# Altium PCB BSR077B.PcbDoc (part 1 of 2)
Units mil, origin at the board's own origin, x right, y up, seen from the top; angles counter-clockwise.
Board outline 2900 x 1600 mil, 4 copper layers (Top Layer, Signal Layer 1, Signal Layer 2, Bottom Layer), stack 40 mil thick; 58 components, 11 nets, 111 pads, 62 vias.
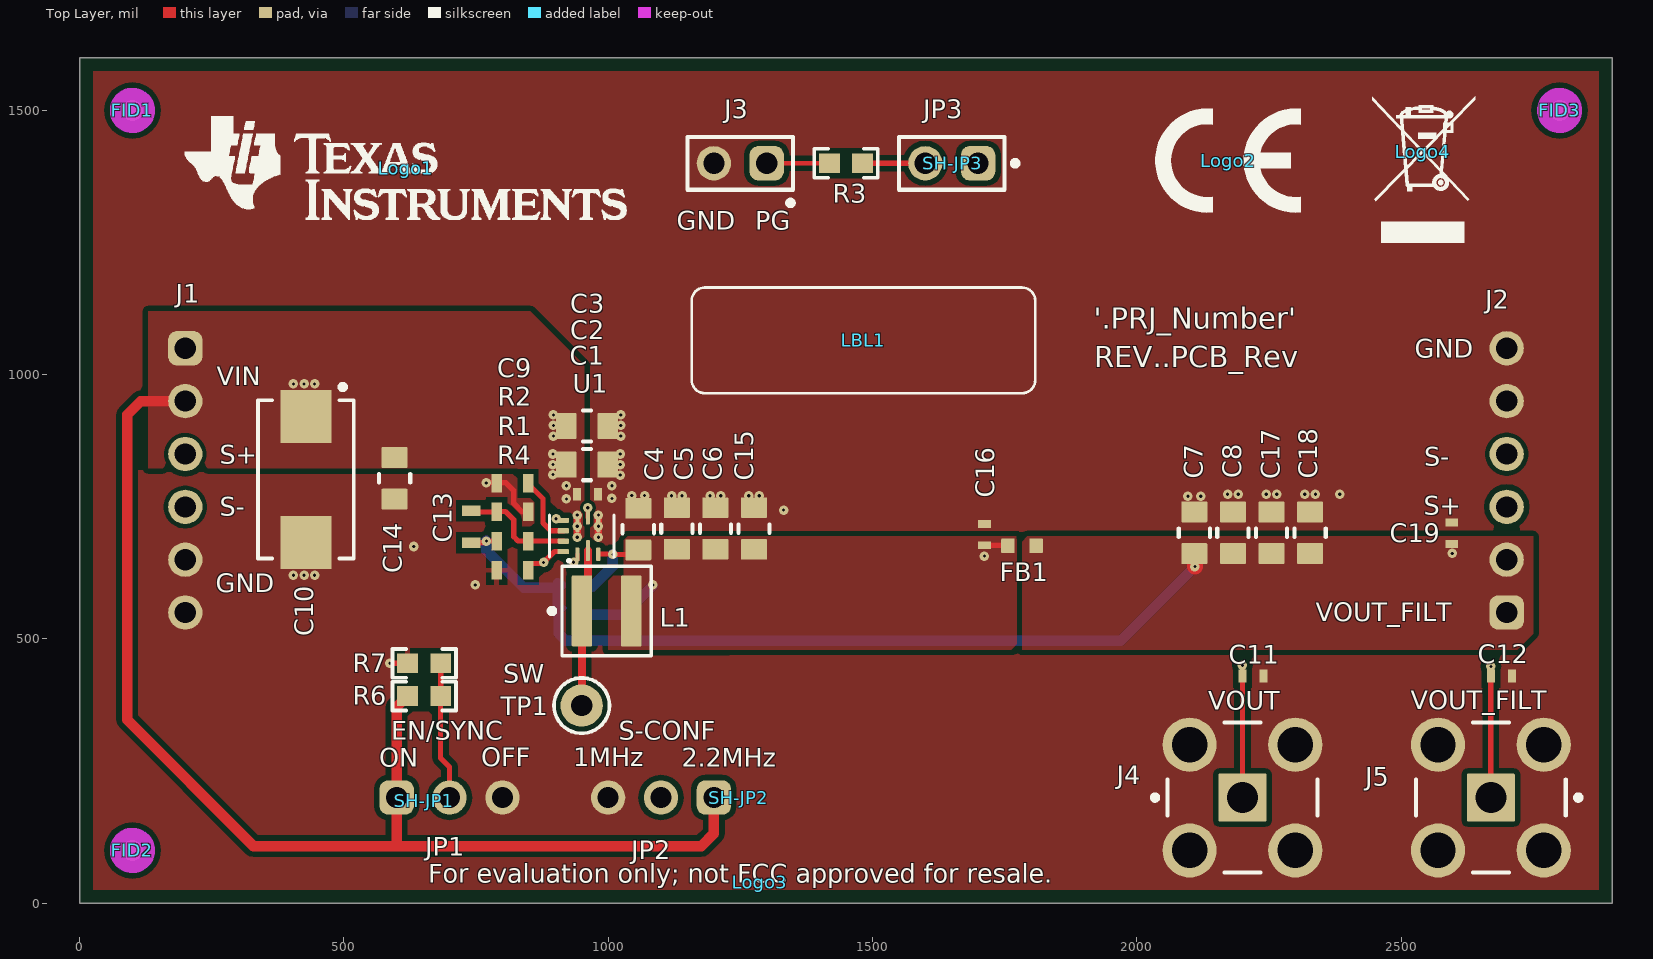
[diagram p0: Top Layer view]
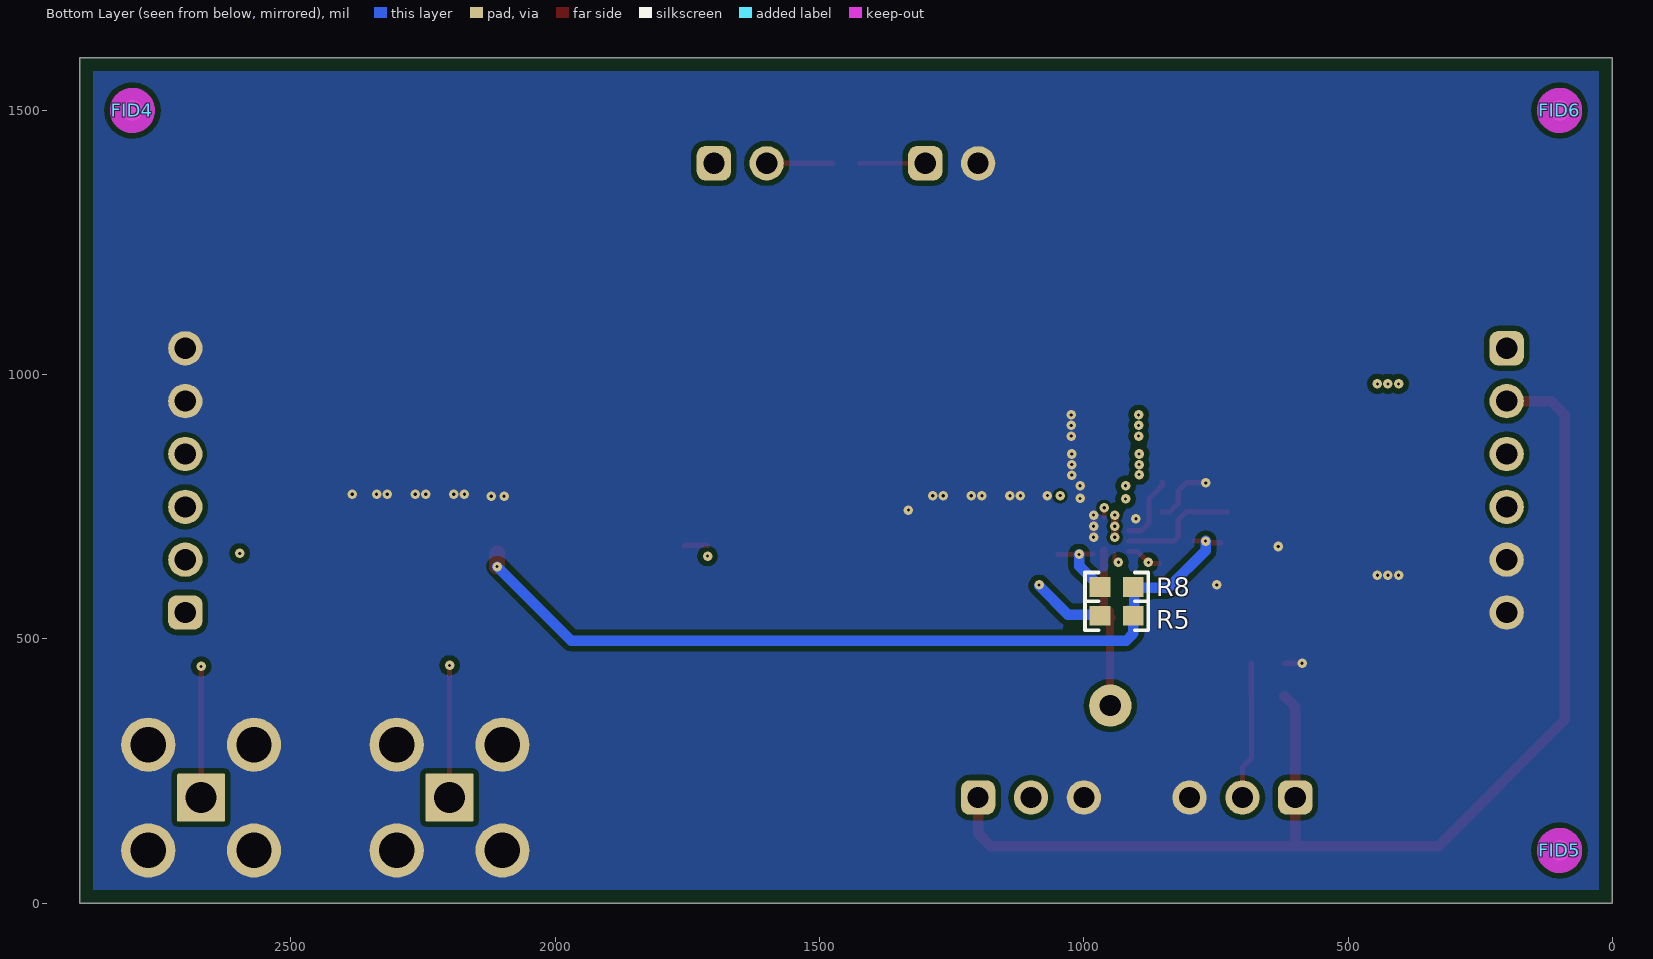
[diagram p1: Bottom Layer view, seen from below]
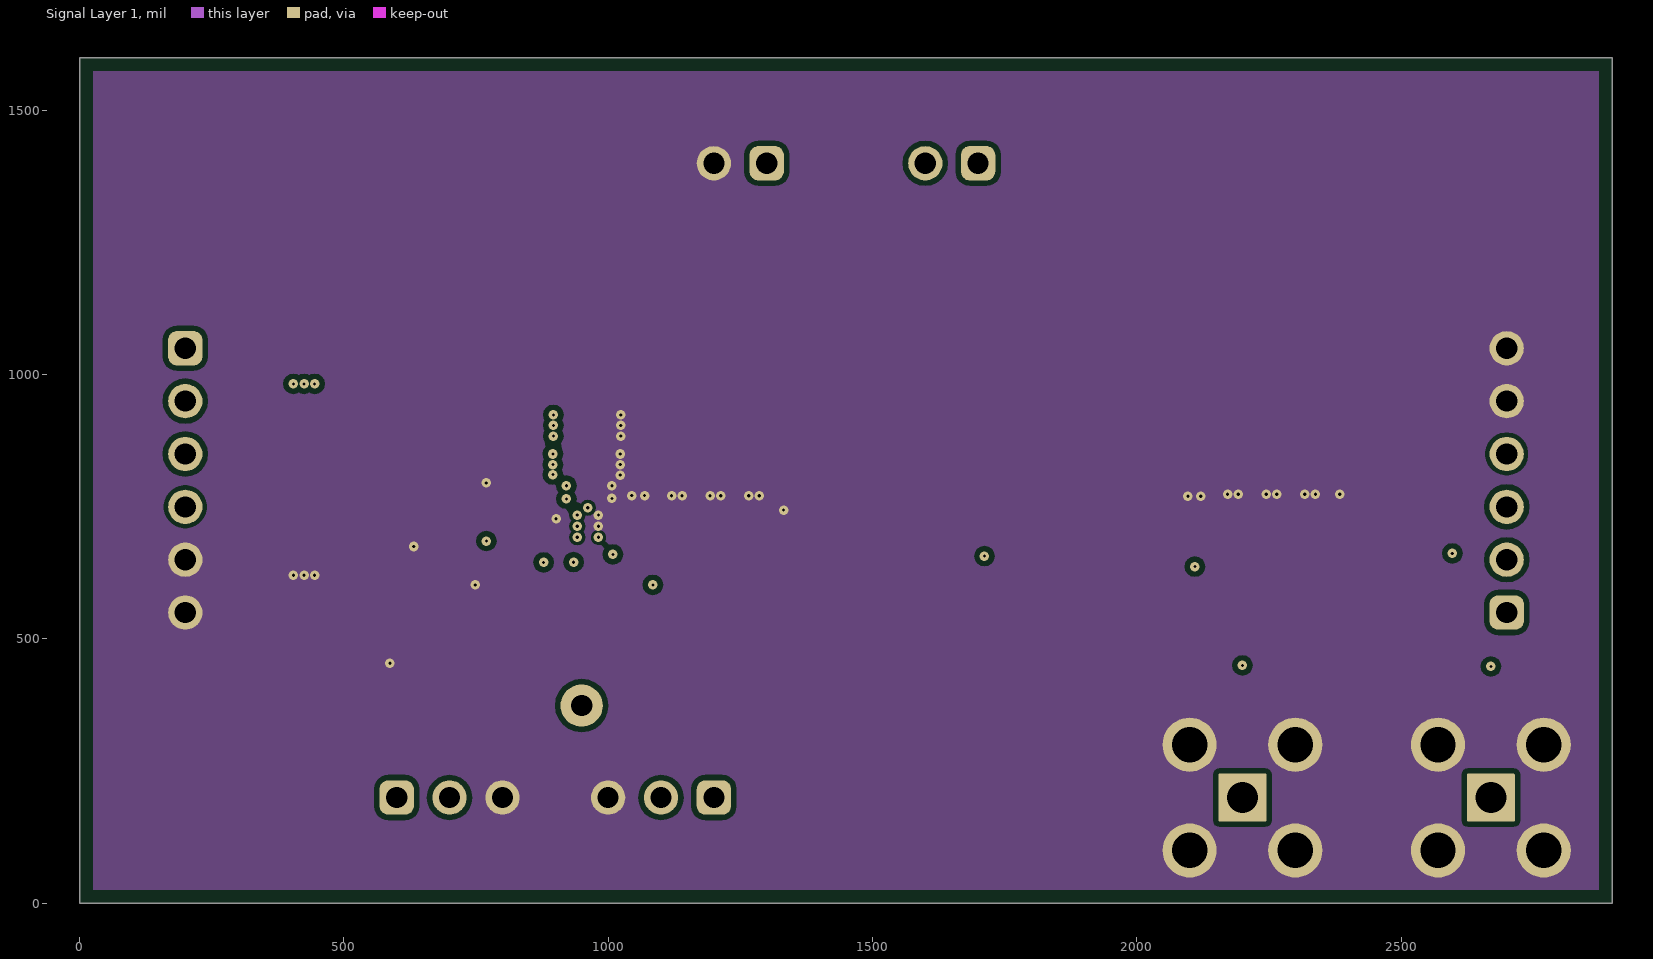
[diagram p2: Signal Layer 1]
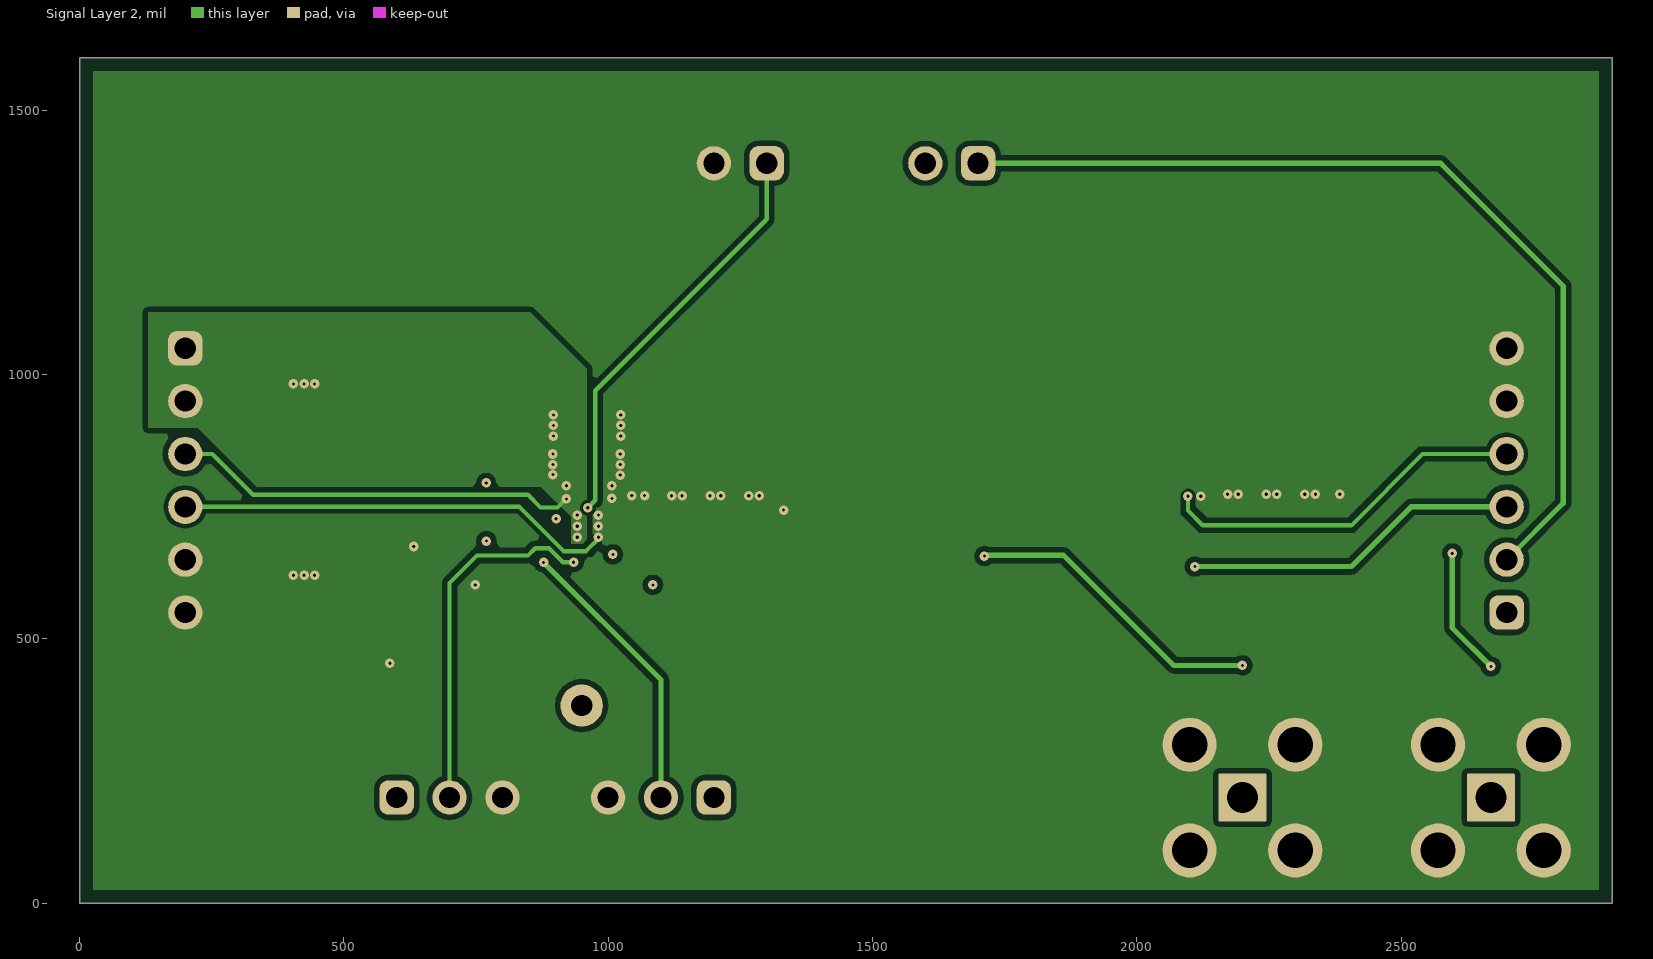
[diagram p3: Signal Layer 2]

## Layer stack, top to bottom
Top Solder: solder mask 0.4, Solder Resist, Dk 3.5
Top Layer: signal copper 1.4
Dielectric 1: prepreg 5, FR-4 High Tg, Dk 4.2
Signal Layer 1: signal copper 1.4
Dielectric 2: core 24.4, FR-4 High Tg, Dk 4.2
Signal Layer 2: signal copper 1.4
Dielectric 3: prepreg 5, FR-4 High Tg, Dk 4.2
Bottom Layer: signal copper 1.4
Bottom Solder: solder mask 0.4, Solder Resist, Dk 3.5

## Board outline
0,0 2900,0 2900,1600 0,1600

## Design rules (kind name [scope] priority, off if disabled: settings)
AcuteAngle [All] p1: minimum=4.50000000000000E+0001 checktracksonly=FALSE
AssemblyTestPointUsage [All] p1: valid=2
BoardOutlineClearance BoardOutlineClearance_MountingHoles [OnCopper and InComponentClass('Mounting Holes')] p1: gap=40 ignorepadtopadclearanceinfootprint=FALSE
BoardOutlineClearance BoardOutlineClearance_Poly [OnCopper and IsPoly] p2: gap=25 ignorepadtopadclearanceinfootprint=FALSE
BoardOutlineClearance [OnCopper and Not InComponentClass('Logo') and not InComponentClass('FiducialMark') and not InRegion(1000,500,4000,800) and not InPoly] p3: gap=40 ignorepadtopadclearanceinfootprint=FALSE
Clearance BGA_Room_1 [WithinRoom('BGA_Room')] p1: gap=5.9 ignorepadtopadclearanceinfootprint=FALSE
Clearance Clearance_JP5 [InComponent('JP4') or InComponent('JP5') or InComponent('JP6') or InComponent('JP7') or InComponent('JP8') or InComponent('JP9') or InComponent('JP10') or InComponent('JP11') or InComponent('JP12') or InComponent('JP13') or InComponent('JP14') or InComponent('JP15') or InComponent('JP16') or InComponent('JP17') or InComponent('JP18') or InComponent('JP19') or InComponent('JP20') or InComponent('JP21') or InComponent('JP22')] p2: gap=5.9 ignorepadtopadclearanceinfootprint=TRUE
Clearance Clearance_FiducialMark [IsKeepOut and InComponentClass('FiducialMark') vs IsPad and InComponentClass('FiducialMark')] p3: gap=0 ignorepadtopadclearanceinfootprint=FALSE
Clearance Clearance_Keepouts [((IsTrack Or IsArc) And Not InPoly) And IsFree and IsKeepOut vs ((IsTrack Or IsArc) And Not InPoly) And IsFree and IsKeepOut] p4: gap=0 ignorepadtopadclearanceinfootprint=FALSE
Clearance Clearance_Poly [InPolygon] p5: gap=10 ignorepadtopadclearanceinfootprint=FALSE except(0: Arc-Hole Track-Hole SMDPad-Hole THPad-Hole Via-Hole Fill-Hole Poly-Hole Region-Hole Text-Hole)
Clearance [All] p6: gap=7.87 ignorepadtopadclearanceinfootprint=FALSE except(0: Arc-Hole Track-Hole SMDPad-Hole THPad-Hole Via-Hole Fill-Hole Poly-Hole Region-Hole Text-Hole)
ComponentClearance ComponentClearance_TI_LOGO [InComponent('Logo1')] p1: gap=0 collisioncheckmode=3 verticalgap=0 showdistances=FALSE
ComponentClearance ComponentClearance_1 [InComponent('JP10') or InComponent('JP11') or InComponent('JP12') Or InComponent('JP13') Or InComponent('JP14') Or InComponent('JP15') Or  InComponent('JP16') or InComponent ('JP17') Or InComponent('JP5') Or InComponent('JP6') Or InComponent('JP7') Or InComponent('JP8') or InComponent('SH-J1') or InComponent('SH-J2') or InComponent('SH-J3') or InComponent('JP22')] p2: gap=0 collisioncheckmode=3 verticalgap=0 showdistances=FALSE
ComponentClearance ComponentClearance_MountingHoles_FiducialMarks [InComponentClass('Mounting Holes') vs InComponentClass('FiducialMark')] p3: gap=50 collisioncheckmode=3 verticalgap=10 showdistances=FALSE
ComponentClearance ComponentClearance_Shunt [InComponentClass('Shunt') vs InComponentClass('Header')] p4: gap=0 collisioncheckmode=3 verticalgap=0 showdistances=FALSE
ComponentClearance ComponentClearance_Logo [InComponentClass('Logo')] p5: gap=30 collisioncheckmode=3 verticalgap=10 showdistances=FALSE
ComponentClearance ComponentClearance_ScrewToNut [(HasFootprint('NY PMS 440 0025 PH')) vs (HasFootprint('Keystone_1902C'))] p6: gap=5 collisioncheckmode=3 verticalgap=10 showdistances=FALSE
ComponentClearance ComponentClearance_MountingHoles [InComponentClass('Mounting Holes')] p7: gap=100 collisioncheckmode=3 verticalgap=100000 showdistances=FALSE
ComponentClearance ComponentClearance_SmallPassives [HasFootprint('0201*') or HasFootprint('0402*') or HasFootprint('0508') or HasFootprint('0603*') or HasFootprint('0612') or HasFootprint('0805*') or HasFootprint('0815*') or HasFootprint('0830*') or HasFootprint('1206*') or HasFootprint('1210*') or HasFootprint('1808*') or HasFootprint('1812*') or HasFootprint('1825*') or HasFootprint('2010*') or HasFootprint('2220*') or HasFootprint('2225*') or HasFootprint('2512*') or HasFootprint('2728*') or HasFootprint('3518*') vs HasFootprint('0201*') or HasFootprint('0402*') or HasFootprint('0508') or HasFootprint('0603*') or HasFootprint('0612') or HasFootprint('0805*') or HasFootprint('0815*') or HasFootprint('0830*') or HasFootprint('1206*') or HasFootprint('1210*') or HasFootprint('1808*') or HasFootprint('1812*') or HasFootprint('1825*') or HasFootprint('2010*') or HasFootprint('2220*') or HasFootprint('2225*') or HasFootprint('2512*') or HasFootprint('2728*') or HasFootprint('3518*')] p8: gap=14.96 collisioncheckmode=3 verticalgap=10 showdistances=FALSE
ComponentClearance ComponentClearance_THtoSMT [IsThruComponent vs IsSMTComponent] p9: gap=20 collisioncheckmode=3 verticalgap=30 showdistances=FALSE
ComponentClearance ComponentClearance_THtoTH [IsThruComponent vs IsThruComponent] p10: gap=20 collisioncheckmode=3 verticalgap=30 showdistances=FALSE
ComponentClearance [All] p11: gap=20 collisioncheckmode=3 verticalgap=10 showdistances=FALSE
DiffPairsRouting [All] p1: maxlimit=100 minlimit=10 mostfreqgap=10 toplayer_minwidth=15 toplayer_maxwidth=15 toplayer_prefwidth=15 midlayer1_minwidth=15 midlayer1_maxwidth=15 midlayer1_prefwidth=15 midlayer2_minwidth=15 midlayer2_maxwidth=15 midlayer2_prefwidth=15 bottomlayer_minwidth=15 bottomlayer_maxwidth=15 bottomlayer_prefwidth=15 maxuncoupledlength=1000
FabricationTestPointUsage TestPointUsage [All] p1: valid=2 allowmultiple=FALSE
FabricationTestpoint Testpoint [All] p1: side=3 testpointundercomponent=TRUE minsize=40 maxsize=100 preferedsize=60 minholesize=0 maxholesize=40 preferedholesize=32 testpointgrid=1 allowsidetop=TRUE allowsidebottom=TRUE usegrid=TRUE gridtolerance=0.01
FanoutControl Fanout_LCC [IsLCC] p1: bgadir=Out bgaviamode=Centered fanoutstyle=Auto fanoutdirection=Alternating viagrid=1 // Fanout_LCC (Default Rule)
FanoutControl Fanout_BGA [IsBGA] p2: bgadir=Out bgaviamode=Centered fanoutstyle=Auto fanoutdirection=Alternating viagrid=1 // Fanout_BGA (Default Rule)
FanoutControl Fanout_Default [All] p4: bgadir=Out bgaviamode=Centered fanoutstyle=Auto fanoutdirection=Alternating viagrid=1 // Fanout_Default (Default Rule)
FanoutControl Fanout_Small [(CompPinCount < 5)] p5: bgadir=Out bgaviamode=Centered fanoutstyle=Auto fanoutdirection=OutThenIn viagrid=1 // Fanout_Small (Default Rule)
HoleSize [All] p1: absolutevalues=TRUE maxlimit=251 minlimit=5.8 maxpercent=80.000 minpercent=20.000
MinimumAnnularRing MinimumAnnularRing_ThermalPadVias [IsVia and InAnyComponent] p1: minimumring=5.91
MinimumAnnularRing [All] p2: minimumring=5.8
MinimumSolderMaskSliver MinimumSolderMaskSliver_Logo [InComponentClass('Logo') vs InComponentClass('Logo')] p1: minsoldermaskwidth=0.7
MinimumSolderMaskSliver [All] p2: minsoldermaskwidth=3.94
PlaneConnect [All] p1: planeconnectstyle=Relief reliefexpansion=10 reliefentries=4 reliefconductorwidth=10 reliefairgap=10
PolygonConnect PolygonConnect_R4 [InComponent('R4') or InComponent('R7')] p1: connectstyle=Relief reliefconductorwidth=10 reliefentries=4 polygonreliefangle="90 Angle" airgapwidth=10
PolygonConnect [All] p2: connectstyle=Direct reliefconductorwidth=10 reliefentries=4 polygonreliefangle="90 Angle" airgapwidth=10
RoomDefinition BGA_Room [False] p1: confinementstyle=ConfineIn formatcopy=TRUE lockcomponents=FALSE outline 1003.35,663.41 1003.35,787.41 922.35,787.41 922.35,663.41
RoutingVias ThermalPadVias [IsVia and InAnyComponent] p1: holewidth=7.87 width=19.68 viastyle="Through Hole" minholewidth=7.87 minwidth=19.68 maxholewidth=12.99 maxwidth=23.62
RoutingVias [All] p2: holewidth=16 width=34 viastyle="Through Hole" minholewidth=5.8 minwidth=18 maxholewidth=40 maxwidth=65
SilkToBoardRegionClearance [Not ((IsComment or IsDesignator) And (Hide <> 'False')) and not InRegion(1000,500,4000,800)] p1:
SilkToSilkClearance SilkToSilkClearance_Pb-FreeLogo [(HasFootprint('Pb-Free_Overlay_Medium') OR HasFootprint('Pb-Free_Overlay_Small')) vs (HasFootprint('Pb-Free_Overlay_Medium') OR HasFootprint('Pb-Free_Overlay_Small'))] p1: silktosilkclearance=0
SilkToSilkClearance [All] p2: silktosilkclearance=4
SilkToSolderMaskClearance SilkToComponentPadClearance [(IsPad or IsFill or IsRegion) and InAnycomponent] p1: minsilkscreentomaskgap=5 clearancetoexposedcopper=TRUE
SilkToSolderMaskClearance "Silk to Solder Mask Opening" [All] p2: minsilkscreentomaskgap=3.94 clearancetoexposedcopper=FALSE
SolderMaskExpansion [All] p1: expansion=1.97
Width [All] p1: maxlimit=100 minlimit=6 preferedwidth=10 checkconnectedcopper=TRUE
15 further rules are at their usual default settings.

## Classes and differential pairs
component class Label: LBL1
component class Shunt: SH-JP1 SH-JP2 SH-JP3
component class BSR077B: C1 C2 C3 C4 C5 C6 C7 C8 C9 C10 C11 C12 C13 C14 C15 C16 C17 C18 C19 FB1 J1 J2 J3 J4 J5 JP1 JP2 JP3 L1 R1 R2 R3 R4 R5 R6 R7 R8 TP1 U1
component class BSR077B_Hardware: !PCB FID1 FID2 FID3 FID4 FID5 FID6 LBL1 Logo1 Logo2 Logo3 Logo4 SH-JP1 SH-JP2 SH-JP3 ZZ1 ZZ2 ZZ3 ZZ4 ZZ5
component class Logo: Logo1
component class FiducialMark: FID1 FID2 FID3 FID4 FID5 FID6
component class AssemblyNote: ZZ1 ZZ2 ZZ3 ZZ4 ZZ5
component class Header: J1 J2 J3 JP1 JP2 JP3

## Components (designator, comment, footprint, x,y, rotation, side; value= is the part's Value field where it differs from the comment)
C1 "GRM155R71H222KA01D" 0402S 961,774 r0 top value=2200pF
C2 "C2012X7S1E106K125AC" 0805_HV1 960,830 r180 top value=10µF
C3 "C2012X7S1E106K125AC" 0805_HV1 960,903 r180 top value=10µF
C4 "C2012X7S1A226M125AC" 0805_HV1 1057,708 r90 top value=22uF
C5 "C2012X7S1A226M125AC" 0805_HV1 1130,709 r90 top value=22uF
C6 "C2012X7S1A226M125AC" 0805_HV1 1203,709 r90 top value=22uF
C7 "C2012X7S1A226M125AC" 0805_HV1 2109,701 r90 top value=22uF
C8 "C2012X7S1A226M125AC" 0805_HV1 2182,701 r90 top value=22uF
C9 "C1608X7R1E474K080AE" 0603S 819,795 r180 top value=0.47uF
C10 "T495X476K035ATE300" 7343-43 428,802 r270 top value=47uF
C11 "GRM1555C1H471JA01D" 0402S 2220,430 r0 top value=470pF
C12 "GRM1555C1H471JA01D" 0402S 2690,430 r0 top value=470pF
C13 "885012206046" 0603S 740.59,712.35 r90 top value=0.1uF
C14 "C2012X7S1E106K125AC" 0805_HV1 596,804 r90 top value=10µF
C15 "C2012X7S1A226M125AC" 0805_HV1 1276,709 r90 top value=22uF
C16 "GRM155R71H222KA01D" 0402S 1712,697.29 r90 top value=2200pF
C17 "C2012X7S1A226M125AC" 0805_HV1 2255,701 r90 top value=22uF
C18 "C2012X7S1A226M125AC" 0805_HV1 2328,701 r90 top value=22uF
C19 "GRM155R71H222KA01D" 0402S 2596,700 r90 top value=2200pF
FB1 "BLE18PS080SN1" FP-BLE18PS080SN1_0603-MFG 1783,676.29 r0 top
FID1 "Fiducial" Fiducial10-20 100,1500 r0 top
FID2 "Fiducial" Fiducial10-20 100,100 r0 top
FID3 "Fiducial" Fiducial10-20 2800,1500 r0 top
FID4 "Fiducial" Fiducial10-20 2800,1500 r180 bottom
FID5 "Fiducial" Fiducial10-20 100,100 r180 bottom
FID6 "Fiducial" Fiducial10-20 100,1500 r180 bottom
J1 "TSW-106-07-G-S" TSW-106-07-G-S 200,800 r270 top
J2 "TSW-106-07-G-S" TSW-106-07-G-S 2700,800 r90 top
J3 "TSW-102-07-G-S" TSW-102-07-G-S 1250,1400 r180 top
J4 "60312002114503" FP-60312002114503_CONN_SMA_PTH-MFG 2200,200 r0 top
J5 "60312002114503" FP-60312002114503_CONN_SMA_PTH-MFG 2670,200 r180 top
JP1 "TSW-103-07-G-S" TSW-103-07-G-S 700,200 r0 top
JP2 "TSW-103-07-G-S" TSW-103-07-G-S 1100,200 r180 top
JP3 "TSW-102-07-G-S" TSW-102-07-G-S 1650,1400 r180 top
L1 "XGL4030-222MEC" FP-XGL4030-222MEC_SMT_IND_4MM0_4MM0-MFG 997,553 r0 top value=2.2µH
LBL1 "THT-14-423-10" Label_650x200 1483,1065 r180 top
Logo1 "Texas Instruments" TI_Stacked_Overlay_Small 617,1391 r0 top
Logo2 "CE Mark" CE_Mark_5mm 2173,1405 r0 top
Logo3 "FCC disclaimer" FCC_disclaimer 1287,40 r0 top
Logo4 "WEEE logo" WEEE_Minimum 2541,1422 r0 top
R1 "CRCW06032K43FKEA" 0603S 819,685 r180 top value=2.43k
R2 "RC0603FR-074K87L" 0603S 819,741 r180 top value=4.87k
R3 "RC0603FR-0710KL" 0603 1450,1400 r0 top value=10.0k
R4 "RC0603FR-0752K3L" 0603S 819,630 r0 top value=52.3k
R5 "ERJ-3EKF49R9V" 0603 938,544 r0 bottom value=49.9
R6 "RC0603FR-071ML" 0603 652,392 r0 top value=1.00Meg
R7 "RC0603FR-071ML" 0603 652,454 r0 top value=1.00Meg
R8 "RCS06030000Z0EA" 0603 938,598.5 r180 bottom value=0
SH-JP1 "60900213421" Wurth_60900213421 652,194 r180 top
SH-JP2 "60900213421" Wurth_60900213421 1247.46,200 r180 top
SH-JP3 "60900213421" Wurth_60900213421 1652,1400 r180 top
TP1 "5002" Keystone5002 950,374 r90 top
U1 "TPS62913RPUR" RPU0010A-MFG 951.74,694.9 r90 top
ZZ1 "This Assembly Note is for PCB labels only" AssemblyNoteLabel 0,2100 r0 top
ZZ2 "These assemblies are ESD sensitive, ESD precautions shall be observed." AssemblyNote 0,2000 r0 top
ZZ3 "These assemblies must be clean and free from flux and all contaminants. Use of no clean flux is not acceptable." AssemblyNote 0,1900 r0 top
ZZ4 "These assemblies must comply with workmanship standards IPC-A-610 Class 2, unless otherwise specified." AssemblyNote 0,1800 r0 top
ZZ5 "Ensure that the inductor is rotated such that the line on the inductor is closest to J1" AssemblyNote 0,1700 r0 top

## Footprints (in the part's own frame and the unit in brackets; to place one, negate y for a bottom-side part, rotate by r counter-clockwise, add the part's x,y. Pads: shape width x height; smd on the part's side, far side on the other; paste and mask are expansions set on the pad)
0402S [mil] "Based on C0402S footprint from PADS legacy"
  rect 15x24 smd: 1(-20,0) 2(20,0)
  body extent -22,-12 22,12, height 24
0603 [mm] "0603 from SM-752 data"
  rect 1x0.95 smd: 1(-0.8,0) 2(0.8,0)
  silkscreen extent -1.52,-0.69 1.52,0.69, body extent -0.87,-0.47 0.87,0.47, height 1
0603S [mil]
  rect 20x35 smd: 1(-30,0) 2(30,0)
  body extent -34,-19 34,19, height 39
0805_HV1 [mm] "Custom footprint based on analyzing multiple manufacturer recommendations"
  rrect10% 1x1.25 smd: 1(-1,0) 2(1,0)
  silkscreen extent -0.2,-0.75 0.2,0.75, body extent -1.1,-0.72 1.1,0.73, height 1.45
7343-43 [mm] "Medium density IPC based on Kemet T495 series"
  rect 2.55x2.45 smd: 1(-3.025,0) 2(3.025,0)
  silkscreen extent -4.56,-2.3 3.8,2.3, body extent -3.8,-2.3 3.8,2.3, height 4.3
AssemblyNote [mil] "Assembly Note"
AssemblyNoteLabel [mil] "Assembly Note for PCB Labels"
CE_Mark_5mm [mil] "Minimum text height for CE Mark"
  silkscreen extent -138,-98 138,98
FCC_disclaimer [mil]
Fiducial10-20 [mm]
  round 1 smd mask+0.5: 1(0,0)
  Top Layer keep-out circle w1.178: c0,0 r0.5
FP-60312002114503_CONN_SMA_PTH-MFG [mm]
  rrect4% 2.3x2.3 hole 1.5 paste-1000 mask+0: 1(0,0)
  round 2.6 hole 1.7 paste-1000 mask+0: 2(-2.54,2.54) 3(2.54,2.54) 4(-2.54,-2.54) 5(2.54,-2.54)
  silkscreen extent -4.32,-3.6 3.6,3.6, body extent -3.94,-3.94 3.94,3.94, height 0.25
FP-BLE18PS080SN1_0603-MFG [mm]
  rrect15% 0.65x0.7 smd paste+0 mask+0: 1(-0.675,0) 2(0.675,0)
  body extent -1.1,-0.58 1.1,0.58, height 0.25
FP-XGL4030-222MEC_SMT_IND_4MM0_4MM0-MFG [mm]
  rrect10% 0.98x3.4 smd paste+0 mask+0: 1(-1.185,0) 2(1.185,0)
  silkscreen extent -2.75,-2.15 2.15,2.15, body extent -2.25,-2.25 2.25,2.25, height 0.25
Keystone5002 [mil] "For Keystone 500x miniature loop terminals"
  round 80 hole 40: 1(0,0)
  silkscreen extent -52,-52 52,52, body extent -49,-49 49,49, height 182
Label_650x200 [mil] "Thermal Transfer Label"
  round 1 on Mech13: 0(0,0)
  silkscreen extent -325,-100 325,100, body extent -325,-100 325,100, height 1
RPU0010A-MFG [mm]
  rrect50% 0.65x0.2 smd paste+0 mask+0: 1(-0.875,0.25) 3(-0.875,-0.75) 5(0.875,-0.25)
  rrect50% 1x0.2 smd paste+0 mask+0: 2(-0.7,-0.25) 4(0.7,-0.75) 6(0.7,0.25)
  rrect40% 0.25x0.55 smd paste+0 mask+0: 7(0.75,0.925) 8(0.25,0.925) 9(-0.25,0.925) 10(-0.75,0.925)
  silkscreen extent -1.25,-1.5 1,1.6, body extent -1.3,-1.15 1.3,1.3, height 0.25
TI_Stacked_Overlay_Small [mil]
  silkscreen extent -418,-98 418,98
TSW-102-07-G-S [mm] "Samtec 100mil, 1x2, 230 mil above insulator"
  rrect50% 1.65x1.65 hole 1.016: 1(-1.27,0)
  round 1.65 hole 1.016: 2(1.27,0)
  silkscreen extent -2.54,-1.27 2.54,2.03, body extent -2.54,-1.27 2.54,1.27, height 8.38
TSW-103-07-G-S [mm] "Samtec 100mil, 1x3, 230 mil above insulator"
  rrect50% 1.65x1.65 hole 1.016: 1(-2.54,0)
  round 1.65 hole 1.016: 2(0,0) 3(2.54,0)
  body extent -3.81,-1.27 3.81,1.27, height 8.38
TSW-106-07-G-S [mm] "Samtec 100mil, 1x6, 230 mil above insulator"
  rrect50% 1.65x1.65 hole 1.016: 1(-6.35,0)
  round 1.65 hole 1.016: 2(-3.81,0) 3(-1.27,0) 4(1.27,0) 5(3.81,0) 6(6.35,0)
  body extent -7.62,-1.27 7.62,1.27, height 8.38
WEEE_Minimum [mil] "WEEElie bin"
  silkscreen extent -95,-172 99,104
Wurth_60900213421 [mil] "Shunt, 2.54mm, Black"
  round 1 on Mech3: 0(0,0)
  body extent -98,-48 98,48, height 338

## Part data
C1 C16 C19: library part CMP-0006683-2, "CAP, CERM, 2200 pF, 50 V, +/- 10%, X7R, 0402", Cap_Case=0402, Manufacturer=MuRata, Supplier Part Number 1=490-1305-1-ND, TempCo=X7R, Tolerance_%=10%, Value1=Unknown, Value2=50V, ValueDisplayed=2200pF
C2 C3 C14: library part CMP-0089528-3, "10µF ±10% 25V Ceramic Capacitor X7S 0805 (2012 Metric)", Digikey Part Number=445-181600-1-ND, Manufacturer=TDK, Mouser Part Number=810-C2012X7S1EK125AC, Operating Temperature Range="-55°C to +125°C", TempCo=22%, Temperature Characteristic=X7S, Tolerance_%=10%, ValueDisplayed=10uF
C4 C5 C6 C7 C8 C15 C17 C18: library part CMP-0007890-2, "CAP, CERM, 22 uF, 10 V, +/- 20%, X7S, 0805", Cap_Case=0805, Manufacturer=TDK, Supplier Part Number 1=445-14560-1-ND, TempCo=X7S, Tolerance_%=20%, Value1="0.00205 ohm", Value2=10V, ValueDisplayed=22uF
C9: library part CMP-0750175-1, "CAP, CERM, 0.47 µF, 25 V,+/- 10%, X7R, 0603", Cap_Case=0603, Manufacturer=TDK, TempCo=X7R, Tolerance_%=10%, Value2=25V, ValueDisplayed=0.47µF
C10: library part CMP-0011835-2, "CAP, TA, 47 uF, 35 V, +/- 10%, 0.3 ohm, SMD", Cap_Case=X, Manufacturer=Kemet, Supplier Part Number 1=399-3905-1-ND, Tolerance_%=10%, Value1="0.3 ohm", Value2=35V, ValueDisplayed=47uF
C11 C12: library part CMP-0006470-2, "CAP, CERM, 470 pF, 50 V, +/- 5%, C0G/NP0, 0402", Cap_Case=0402, Manufacturer=MuRata, Supplier Part Number 1=490-1297-1-ND, TempCo=C0G/NP0, Tolerance_%=5%, Value1=Unknown, Value2=50V, ValueDisplayed=470pF
C13: library part CMP-0006829-4, "CAP, CERM, 0.1 uF, 16 V, +/- 10%, X7R, 0603", Cap_Case=0603, Manufacturer="Wurth Elektronik", Supplier Part Number 1=710-885012206046, TempCo=X7R, Tolerance_%=10%, Value1=Unknown, Value2=16V, ValueDisplayed=0.1uF
FB1: library part CMP-0087072-1, "Bead inductor BLE series, 8A", Manufacturer=Murata
FID1 FID2 FID3 FID4 FID5 FID6: library part CMP-0077181-1, "Fiducial mark.  There is nothing to buy or mount.", Manufacturer=N/A
J1 J2: library part CMP-0075413-2, "Header, 100mil, 6x1, Gold, TH", Color=Black, Current_A=6.3A, Manufacturer=Samtec, Supplier Part Number 1=SAM1029-06-ND, Voltage_V=550V
J3 JP3: library part CMP-0075405-3, "Header, 100mil, 2x1, Gold, TH", Color=Black, Current_A=6.3A, Manufacturer=Samtec, Supplier Part Number 1=SAM1029-02-ND, Voltage_V=550V
J4 J5: library part CMP-0089038-2, "SMA Connector Jack, Female Socket 50Ohm Through Hole Solder", Manufacturer="Wurth Electronics", Voltage_V=335V
JP1 JP2: library part CMP-0075407-2, "Header, 100mil, 3x1, Gold, TH", Color=Black, Current_A=6.3A, Manufacturer=Samtec, Supplier Part Number 1=SAM1029-03-ND, Voltage_V=550V
L1: library part CMP-0089541-3, "Inductor Power Shielded Wirewound 2.2uH 20% 1MHz Composite 8.7A 15mOhm DCR Automotive T/R", Manufacturer=Coilcraft, Operating Temperature Range="to +165°C", Self Resonant Frequency=40MHz, Test Frequency=1MHz, Tolerance_%=20%
LBL1: library part CMP-0003625-1, "Thermal Transfer Printable Labels, 0.650\" W x 0.200\" H - 10,000 per roll", Manufacturer=Brady, Supplier Part Number 1=97C5133
Logo1: library part CMP-0074838-1, "Texas Instrument Corporate Signature"
Logo2: library part CMP-0074844-1
Logo3: library part CMP-0074847-1, "FCC_disclaimer"
Logo4: library part CMP-0074769-1
R1: library part CMP-0022276-4, "RES, 2.43 k, 1%, 0.1 W, AEC-Q200 Grade 0, 0603", Manufacturer=Vishay-Dale, Power_W=100mW, Supplier Part Number 1=541-2.43KHCT-ND, TempCo="100 ppm/C", Tolerance_%=1%, Value2=0.1W, Value_Code=2k43, ValueDisplayed=2.43k
R2: library part CMP-0023154-5, "RES, 4.87 k, 1%, 0.1 W, 0603", Manufacturer=Yageo, Power_W=100mW, Supplier Part Number 1=311-4.87KHRCT-ND, TempCo="100 ppm/C", Tolerance_%=1%, Value2=0.1W, Value_Code=4k87, ValueDisplayed=4.87k
R3: library part CMP-0022746-5, "RES, 10.0 k, 1%, 0.1 W, 0603", Manufacturer=Yageo, Power_W=100mW, Supplier Part Number 1=311-10.0KHRCT-ND, TempCo="100 ppm/C", Tolerance_%=1%, Value2=0.1W, Value_Code=10k0, ValueDisplayed=10.0k
R4: library part CMP-0023172-5, "RES, 52.3 k, 1%, 0.1 W, 0603", Manufacturer=Yageo, Power_W=100mW, Supplier Part Number 1=311-52.3KHRCT-ND, TempCo="100 ppm/C", Tolerance_%=1%, Value2=0.1W, Value_Code=52k3, ValueDisplayed=52.3k
R5: library part CMP-0022707-2, "RES, 49.9, 1%, 0.1 W, AEC-Q200 Grade 0, 0603", Manufacturer=Panasonic, Power_W=100mW, Supplier Part Number 1=P49.9HCT-ND, TempCo="100 ppm/C", Tolerance_%=1%, Value2=0.1W, Value_Code=49R9, ValueDisplayed=49.9
R6 R7: library part CMP-0022899-4, "RES, 1.00 M, 1%, 0.1 W, 0603", Manufacturer=Yageo, Power_W=100mW, Supplier Part Number 1=311-1.00MHRCT-ND, TempCo="100 ppm/C", Tolerance_%=1%, Value2=0.1W, Value_Code=1M00, ValueDisplayed=1.00M
R8: library part CMP-0081973-1, "RES, 0, 0%, 0.25 W, AEC-Q200 Grade 0, 0603", Manufacturer=Vishay-Dale, Power_W=250mW, Supplier Part Number 1=541-2779-1-ND, Tolerance_%=0%, Value2=0.25W, Value_Code=0
SH-JP1 SH-JP2 SH-JP3: library part CMP-0003761-2, "Shunt, 2.54mm, Gold, Black", Manufacturer="Wurth Elektronik", Supplier Part Number 1=732-2678-ND
TP1: library part CMP-0055139-1, "Test Point, Miniature, White, TH", Color=White, Manufacturer=Keystone, Supplier Part Number 1=36-5002-ND
U1: library part CMP-0089785-1, "3V to 17V, 3A Micro Noise (20µVRMS) and Micro Ripple (200µVPP) buck converter", Manufacturer="Texas Instruments", Max Supply Voltage=17V, Min Supply Voltage=3V, Nominal Supply Current=5mA, Operating Temperature Range="-40°C to +150°C", Output Voltage=0.8-5.5V, Switching Frequency=1/2.2MHz
ZZ1: library part CMP-0003616-3
ZZ2: library part CMP-0077236-1
ZZ3: library part CMP-0077237-1
ZZ4: library part CMP-0077238-1
ZZ5: library part CMP-0077238-1, "Special instruction for inductor L1 assembly"

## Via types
v1: diameter 18, hole 6, Top Layer to Bottom Layer, tented both sides, 53 vias
v2: diameter 18, hole 6.1, Top Layer to Bottom Layer, tented both sides, 9 vias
